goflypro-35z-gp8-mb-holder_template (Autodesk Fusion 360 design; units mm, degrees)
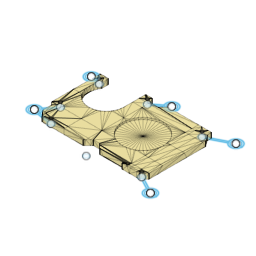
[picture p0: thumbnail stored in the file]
base_mesh_feature "Grundnetzelement"
modify "Ändern1"
modify "Ändern2"
modify "Ändern4"
modify "Ändern5"
sketch "Skizze" plane through (0, 0, 0) normal (0, 0, 1) x axis (1, 0, 0)
  line L1 (20.5229, -16.782) -> (25.8481, -19.6013)
  line L2 (26.1901, -18.9175) -> (20.8967, -16.115)
  line L3 (18.6933, 16.1472) -> (26.1697, 19.9476)
  line L4 (25.8377, 20.6326) -> (18.4134, 16.8587)
  line L5 (-8.6571, 16.9031) -> (-5.054, 19.5971)
  line L6 (-5.4965, 20.2321) -> (-9.1025, 17.5358)
  line L7 (-33.4754, -11.5659) -> (-30.5019, -7.4733)
  line L8 (-31.152, -7.007) -> (-34.1054, -11.072)
  line L9 (-32.8621, 13.5611) -> (-31.8149, 13.2805)
  line L10 (-31.5775, 14.0451) -> (-32.7042, 14.347)
  line L11 (-32.8739, -14.4713) -> (-26.7524, -15.5507)
  line L12 (-26.6048, -14.7644) -> (-32.7064, -13.6885)
  circle C1 centre (-30.415, 13.265) radius 0.6
  circle C2 centre (-30.045, -6.15) radius 0.6
  circle C3 centre (-25.36, -15.405) radius 0.6
  circle C4 centre (19.535, -15.79) radius 0.6
  circle C5 centre (-9.98, 16.445) radius 0.6
  circle C6 centre (17.3, 16.01) radius 0.6
  circle C7 centre (-35.5, 14.5) radius 1.05
  circle C8 centre (-35.5, -13.5) radius 1.05
  circle C9 centre (-3, 21.5) radius 1.05
  circle C10 centre (28.5, 21.5) radius 1.05
  circle C11 centre (28.5, -20.5) radius 1.05
  circle C12 centre (-3, -20.5) radius 1.05
  circle C13 centre (-35.5, 14.5) radius 2
  circle C14 centre (-3, 21.5) radius 2
  circle C15 centre (28.5, 21.5) radius 2
  circle C16 centre (-35.5, -13.5) radius 2
  circle C17 centre (28.5, -20.5) radius 2
  circle C18 centre (28.5, -20.5) radius 2.8
  circle C19 centre (-35.5, -13.5) radius 2.8
  circle C20 centre (-3, 21.5) radius 2.8
  circle C21 centre (28.5, 21.5) radius 2.8
  circle C22 centre (17.3, 16.01) radius 1.4
  circle C23 centre (-9.98, 16.445) radius 1.4
  circle C24 centre (19.535, -15.79) radius 1.4
  circle C25 centre (-25.36, -15.405) radius 1.4
  circle C26 centre (-30.045, -6.15) radius 1.4
  circle C27 centre (-30.415, 13.265) radius 1.4
  circle C28 centre (-35.5, 14.5) radius 2.8
  point P30 (26.1901, -18.9175)
  point P31 (25.8481, -19.6013)
  point P32 (20.8967, -16.115)
  point P33 (20.5229, -16.782)
  point P34 (26.1697, 19.9476)
  point P35 (25.8377, 20.6326)
  point P36 (18.6933, 16.1472)
  point P37 (18.4134, 16.8587)
  point P38 (-9.1025, 17.5358)
  point P39 (-8.6571, 16.9031)
  point P40 (-5.054, 19.5971)
  point P41 (-5.4965, 20.2321)
  point P42 (-33.4754, -11.5659)
  point P43 (-34.1054, -11.072)
  point P44 (-31.152, -7.007)
  point P45 (-30.5019, -7.4733)
  point P47 (-32.7042, 14.347)
  point P48 (-32.8621, 13.5611)
  point P49 (-31.8149, 13.2805)
  point P50 (-31.5775, 14.0451)
  point P51 (-26.7524, -15.5507)
  point P52 (-26.6048, -14.7644)
  point P53 (-32.8739, -14.4713)
  point P54 (-32.7064, -13.6885)
  concentric C7 C13
  concentric C9 C14
  concentric C10 C15
  concentric C11 C17
  concentric C17 C18
  concentric C9 C20
  concentric C10 C21
  concentric C6 C22
  concentric C5 C23
  concentric C4 C24
  concentric C3 C25
  concentric C2 C26
  concentric C1 C27
  parallel L1 L2
  coincident C18 P30
  coincident C18 P31
  coincident C24 P32
  coincident C24 P33
  parallel L3 L4
  coincident C21 P34
  coincident C21 P35
  coincident C22 P36
  coincident C22 P37
  parallel L5 L6
  coincident C23 P38
  coincident C23 P39
  coincident C20 P40
  coincident C20 P41
  coincident C19 P42
  coincident C19 P43
  coincident C26 P44
  coincident C26 P45
  concentric C7 C28
  coincident C28 P47
  coincident C28 P48
  coincident C27 P49
  coincident C27 P50
  coincident C25 P51
  coincident C25 P52
  coincident C19 P53
  coincident C19 P54
  dimension "d1" diameter C1 = 1.2
  dimension "d2" diameter C2 = 1.2
  dimension "d3" diameter C3 = 1.2
  dimension "d5" diameter C4 = 1.2
  dimension "d6" diameter C5 = 1.2
  dimension "d7" diameter C6 = 1.2
  dimension "d12" diameter C9 = 2.1
  dimension "d13" diameter C7 = 2.1
  dimension "d14" diameter C8 = 2.1
  dimension "d15" diameter C13 = 4
  dimension "d16" diameter C14 = 4
  dimension "d17" diameter C15 = 4
  dimension "d18" diameter C16 = 4
  dimension "d19" diameter C17 = 4
  dimension "d20" diameter C18 = 5.6
  dimension "d21" diameter C19 = 5.6
  dimension "d23" diameter C20 = 5.6
  dimension "d24" diameter C21 = 5.6
  dimension "d26" diameter C22 = 2.8
  dimension "d27" diameter C23 = 2.8
  dimension "d28" diameter C24 = 2.8
  dimension "d30" diameter C25 = 2.8
  dimension "d31" diameter C26 = 2.8
  dimension "d32" diameter C27 = 2.8
  dimension "d51" diameter C28 = 5.6
  dimension "d10" R-Pattern1-uDistance = 31.5
  dimension "d11" R-Pattern1-vDistance = -42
